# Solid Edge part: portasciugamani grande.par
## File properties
Last saved by: i.fialdini
Revision: 62
Tipo di contenuto documento: 0
Accuracy: 0.990
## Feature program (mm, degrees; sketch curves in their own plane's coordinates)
body "unnamed Body 1"
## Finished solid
Body 1: solid body, 10 faces, 24 edges, 16 vertices.
  Faces by surface: plane 7, cylinder 3
  Edges by curve: line 18, circle 6
Bounding box of the edges (mm): 45.000 x 386.500 x 2.000, from (302.5, -210, -147) to (347.5, 176.5, -145).
Cylindrical faces by radius (mm): R5 x2, R33.5 x1
Planar faces by outward normal: +x 2, +y 1, +z 1, -x 2, -z 1
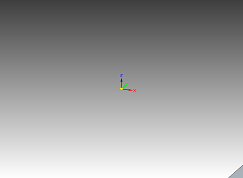
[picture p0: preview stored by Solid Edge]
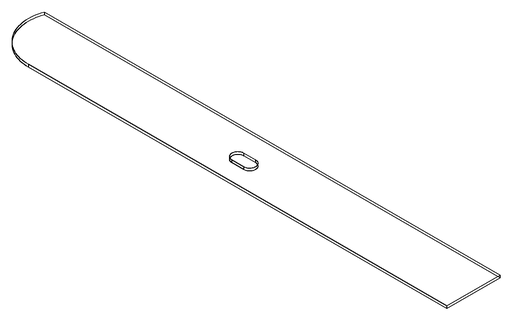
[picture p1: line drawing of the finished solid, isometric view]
